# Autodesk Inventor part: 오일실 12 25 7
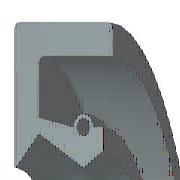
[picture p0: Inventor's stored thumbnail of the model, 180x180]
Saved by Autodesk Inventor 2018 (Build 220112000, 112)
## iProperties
IsCustomPart: 1
Created: 2012-02
Part Number: 오일실 12 25 7
Material: 고무
Description: 오일-실
Document SubType Name: Modeling
Standard: KS B 2804
Designer: test
Standards Organization: KS
Language: ko-KR
Size Designation: D - 12 25 7
Categories: <MemberInstance><Categories><Category DisplayName="샤프트 부품" InternalName="7f7aeb1f-a693-4053-b835-cee3144e0d98" Mnemonic="SHFT"><Category DisplayName="실링" Intern
Density: 0.93 g/cm^3
Appearance: 고무 - 검은색 - 버전 1.1
Author: test
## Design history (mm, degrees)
revolve "본체" stored, may be unused: angle "d17" = 90 deg
revolve "스프링1" stored, may be unused: angle "d18" = 90 deg
body "Solid1"
sketch "스케치1"
  geometry: L1 (0, 12.5)-(7, 12.5); L2 (7, 10.75)-(1.75, 10.75); L3 (1.75, 7.75)-(4.9, 6); L4 (4.9, 6)-(0, 6); L5 (0, 0)-(9.586, 0) reference; L6 (4.9, 6)-(6.3, 6.875); L7 (0, 18)-(0, -3) reference; L8 (-1.941, 0)-(11.507, 0) reference; L9 (4.2, 8.1)-(1.75, 8.59); L10 (1.75, 8.59)-(1.75, 10.75); L11 (0, 12.5)-(0, 6.088); L12 (4.9, 6)-(0, 6); L13 (1.75, 7.75)-(0.152, 6.028); L14 (7, 12.5)-(7, 10.75); L15 (5.6, 8.1)-(6.3, 8.1); L16 (6.3, 8.1)-(6.3, 6.875); C1 r 0.455 at (4.9, 8.1); A1 r 0.7 centre (4.9, 8.1) between (5.6, 8.1) and (4.2, 8.1); A2 r 0.088 centre (0.088, 6.088) between (0, 6.088) and (0.152, 6.028); 1 further point
  constraints: 28 end point, 5 horizontal alignment, 5 point on line, 4 point on circle, 4 vertical alignment, 3 centre point, 3 tangent, 2 collinear, 2 horizontal, 2 perpendicular, 1 coincident, 1 parallel
  dimensions: "d0" = 25 diameter of L1 L5 (= SD2); "d1" = 1.75 distance of L1.end L2.start (= SD); "d2" = 0.91 diameter of C1 (= SPDI); "d3" = 1.4 diameter of A1 (= SPDA); "d4" = 12 diameter of L3.end L5 (= NND); "d5" = 15.5 diameter of L3.start L5 (= TKDM); "d7" = 17.18 diameter of L9.end L5 (= TKDM + 0.24 x SWDT); "d8" = 1.75 distance between parallel lines of L11 L10 (= SD); "d9" = 4.9 distance from line of L11 C1.centre (= SPDST); "d10" = 16.2 diameter of C1.centre L5 (= HLDM); "d11" = 0.0875 radius of A2 (= 0.25 x LAB); "d12" = 6.3 distance between parallel lines of L11 L16 (= SDI); "d13" = 13.75 diameter of L6.end L5 (= ABDM); "d14" = 7 distance from line of L11 L1.end (= SWDT)
fillet "모깎기1" dims "d6" = 0.3 (= RR)
other parameters: "SD2" = 25 [user parameter; used in 1 equation term], "SWDT" = 7 [user parameter; used in 2 equation terms], "RR" = 0.3 [user parameter; used in 1 equation term], "SD" = 1.75 [user parameter; used in 2 equation terms], "NND" = 12 [user parameter; used in 1 equation term], "SPDA" = 1.4 [user parameter; used in 1 equation term], "SPDI" = 0.91 [user parameter; used in 1 equation term], "TKDM" = 15.5 [user parameter; used in 2 equation terms], "HLDM" = 16.2 [user parameter; used in 1 equation term], "ABDM" = 13.75 [user parameter; used in 1 equation term], "SDI" = 6.3 [user parameter; used in 1 equation term], "SPDST" = 4.9 [user parameter; used in 1 equation term], "LAB" = 0.35 [user parameter; used in 1 equation term], "d15" = 0, "d16" = 0, "d19" = 0
